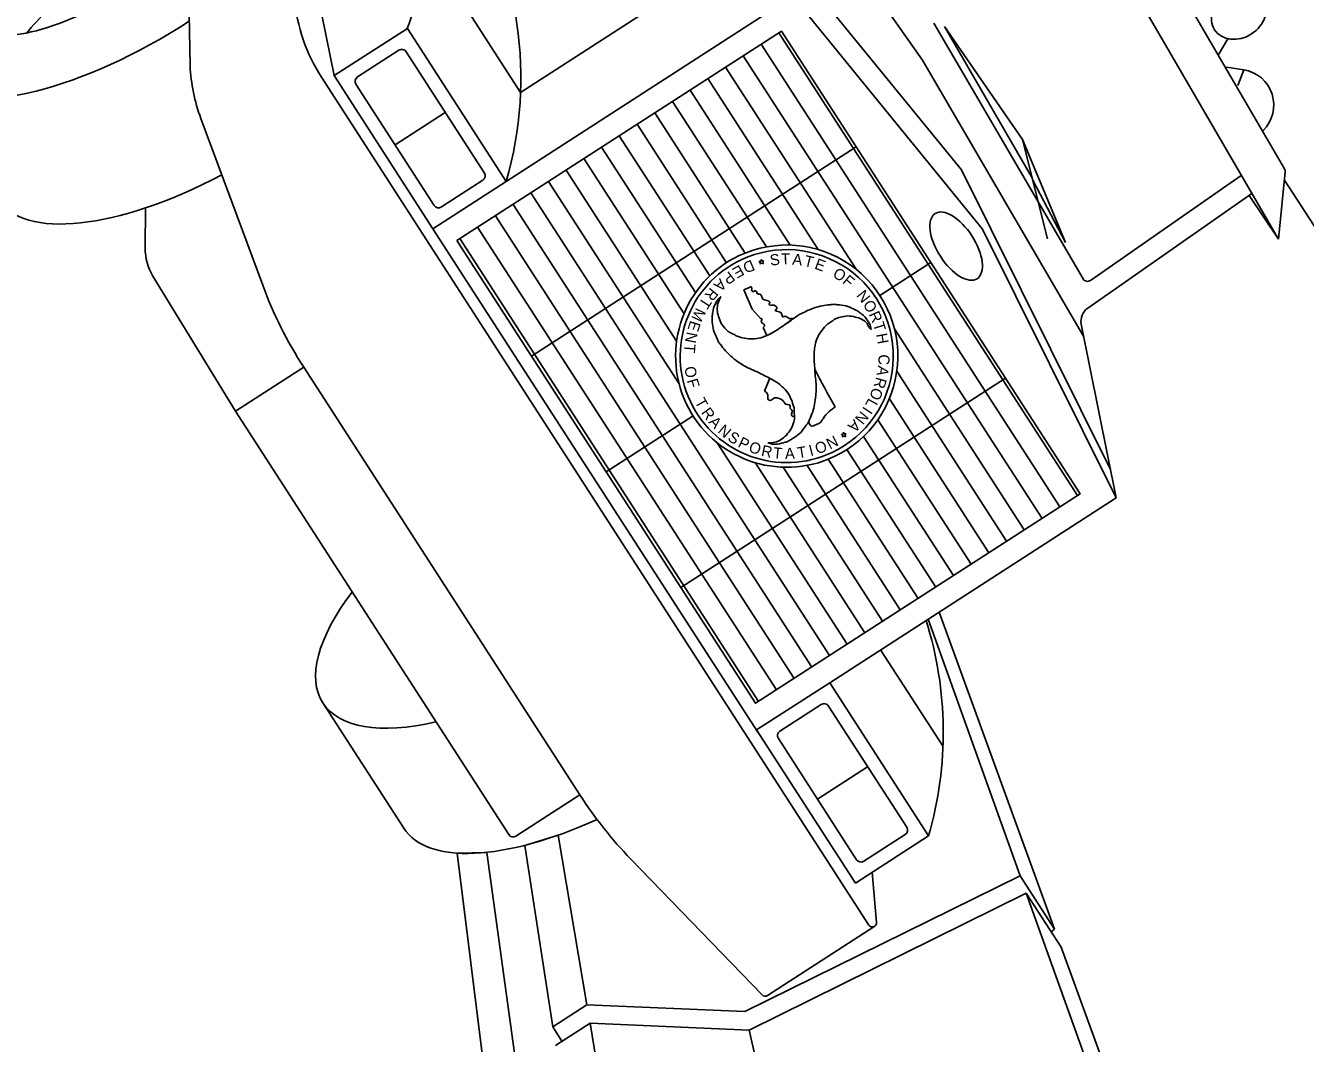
# Model space of a CAD drawing. Extents: x 2160312 to 2162215, y 789569 to 792090.
# Drawn here: x 2160615.79 to 2160662.65, y 791228.56 to 791265.83 of the extents above; entities that cross this region are included whole.
import ezdxf

# ---------------------------------------------------------------- set-up
doc = ezdxf.new("R2010")
doc.units = 0
doc.layers.add('DEV TITLE SHEET CELL', color=7, linetype='Continuous')

msp = doc.modelspace()

# ---------------------------------------------------------------- linework, layer by layer
at = {"layer": 'DEV TITLE SHEET CELL'}
for p, q in [((2160648.626, 791264.563), (2160640.264, 791276.54)), ((2160655.676, 791271.234), (2160661.886, 791260.593)), ((2160627.088, 791263.999), (2160625.964, 791269.539)), ((2160642.535, 791268.951), (2160633.917, 791263.388)), ((2160643.297, 791268.831), (2160650.056, 791260.549)), ((2160630.476, 791268.718), (2160633.917, 791263.388)), ((2160655.437, 791268.714), (2160661.659, 791258.006)), ((2160621.816, 791264.365), (2160621.745, 791268.133)), ((2160643.446, 791266.614), (2160633.389, 791260.122)), ((2160649.047, 791265.919), (2160654.507, 791256.561)), ((2160654.304, 791248.623), (2160643.367, 791265.566)), ((2160652.295, 791261.665), (2160649.431, 791265.803)), ((2160649.431, 791265.803), (2160652.654, 791260.228)), ((2160653.655, 791248.205), (2160642.718, 791265.147)), ((2160659.812, 791265.35), (2160659.457, 791264.755)), ((2160627.945, 791263.954), (2160629.458, 791264.93)), ((2160629.725, 791264.873), (2160632.59, 791260.434)), ((2160653.007, 791247.786), (2160642.07, 791264.729)), ((2160648.626, 791264.563), (2160654.537, 791254.434)), ((2160646.197, 791256.912), (2160641.422, 791264.31)), ((2160660.391, 791264.212), (2160659.765, 791264.311)), ((2160660.391, 791264.212), (2160660.176, 791263.635)), ((2160630.753, 791259.248), (2160627.888, 791263.687)), ((2160644.814, 791257.632), (2160640.773, 791263.892)), ((2160643.789, 791257.797), (2160640.125, 791263.473)), ((2160631.157, 791262.653), (2160629.32, 791261.467)), ((2160642.914, 791257.729), (2160639.476, 791263.054)), ((2160624.474, 791256.33), (2160622.21, 791262.434)), ((2160641.452, 791257.147), (2160638.179, 791262.217)), ((2160642.141, 791257.504), (2160638.828, 791262.636)), ((2160640.844, 791256.666), (2160637.531, 791261.799)), ((2160646.197, 791261.392), (2160634.319, 791253.724)), ((2160640.321, 791256.053), (2160636.882, 791261.38)), ((2160653.207, 791258.019), (2160652.295, 791261.665)), ((2160652.295, 791261.665), (2160653.865, 791257.889)), ((2160639.9, 791255.282), (2160636.234, 791260.961)), ((2160639.63, 791254.278), (2160635.585, 791260.543)), ((2160650.056, 791260.549), (2160655.516, 791249.582)), ((2160654.785, 791256.5), (2160660.297, 791260.349)), ((2160661.659, 791258.006), (2160661.911, 791260.477)), ((2160632.533, 791260.167), (2160631.02, 791259.19)), ((2160639.722, 791252.711), (2160634.937, 791260.124)), ((2160653.865, 791257.889), (2160652.67, 791260.167)), ((2160661.88, 791260.176), (2160704.37, 791194.597)), ((2160645.225, 791242.763), (2160634.288, 791259.706)), ((2160654.679, 791255.485), (2160660.687, 791259.68)), ((2160660.592, 791259.614), (2160661.659, 791258.006)), ((2160620.174, 791257.682), (2160620.187, 791259.156)), ((2160644.577, 791242.344), (2160633.64, 791259.287)), ((2160643.28, 791241.507), (2160632.343, 791258.45)), ((2160643.928, 791241.926), (2160632.992, 791258.868)), ((2160630.708, 791258.391), (2160642.605, 791239.961)), ((2160642.632, 791241.089), (2160631.695, 791258.031)), ((2160642.642, 791257.193), (2160642.712, 791257.203)), ((2160642.642, 791257.193), (2160642.712, 791257.203)), ((2160642.703, 791257.161), (2160642.642, 791257.193)), ((2160642.703, 791257.161), (2160642.642, 791257.193)), ((2160642.69, 791257.091), (2160642.703, 791257.161)), ((2160642.69, 791257.091), (2160642.703, 791257.161)), ((2160642.741, 791257.14), (2160642.69, 791257.091)), ((2160642.741, 791257.14), (2160642.69, 791257.091)), ((2160642.712, 791257.203), (2160642.726, 791257.272)), ((2160642.712, 791257.203), (2160642.726, 791257.272)), ((2160642.726, 791257.272), (2160642.756, 791257.208)), ((2160642.726, 791257.272), (2160642.756, 791257.208)), ((2160642.804, 791257.105), (2160642.741, 791257.14)), ((2160642.804, 791257.105), (2160642.741, 791257.14)), ((2160642.756, 791257.208), (2160642.823, 791257.218)), ((2160642.756, 791257.208), (2160642.823, 791257.218)), ((2160642.823, 791257.218), (2160642.774, 791257.169)), ((2160642.823, 791257.218), (2160642.774, 791257.169)), ((2160642.774, 791257.169), (2160642.804, 791257.105)), ((2160642.774, 791257.169), (2160642.804, 791257.105)), ((2160648.931, 791257.156), (2160647.069, 791255.954)), ((2160623.473, 791251.71), (2160620.456, 791256.662)), ((2160642.092, 791256.16), (2160642.317, 791256.256)), ((2160642.092, 791256.16), (2160642.317, 791256.256)), ((2160642.395, 791255.449), (2160642.092, 791256.16)), ((2160642.395, 791255.449), (2160642.092, 791256.16)), ((2160642.702, 791255.105), (2160642.395, 791255.449)), ((2160642.702, 791255.105), (2160642.395, 791255.449)), ((2160642.935, 791254.483), (2160642.801, 791254.775)), ((2160642.935, 791254.483), (2160642.801, 791254.775)), ((2160646.76, 791254.716), (2160646.75, 791254.719)), ((2160646.76, 791254.716), (2160646.75, 791254.719)), ((2160646.76, 791254.716), (2160646.75, 791254.719)), ((2160652.358, 791247.368), (2160647.605, 791254.731)), ((2160655.726, 791248.545), (2160654.443, 791254.896)), ((2160625.978, 791253.327), (2160623.473, 791251.71)), ((2160625.978, 791253.327), (2160636.089, 791237.663)), ((2160651.666, 791252.921), (2160639.787, 791245.253)), ((2160642.849, 791252.452), (2160643.038, 791252.919)), ((2160642.849, 791252.452), (2160643.038, 791252.919)), ((2160643.038, 791252.919), (2160643.038, 791252.919)), ((2160643.038, 791252.919), (2160643.038, 791252.919)), ((2160644.686, 791253.255), (2160644.686, 791253.255)), ((2160644.686, 791253.255), (2160644.686, 791253.255)), ((2160651.71, 791246.949), (2160647.692, 791253.173)), ((2160651.062, 791246.53), (2160647.42, 791252.171)), ((2160623.473, 791251.71), (2160633.48, 791236.208)), ((2160640.232, 791251.541), (2160637.053, 791249.489)), ((2160650.413, 791246.112), (2160646.998, 791251.402)), ((2160645.738, 791250.942), (2160645.726, 791250.872)), ((2160645.738, 791250.942), (2160645.726, 791250.872)), ((2160645.768, 791250.879), (2160645.738, 791250.942)), ((2160645.768, 791250.879), (2160645.738, 791250.942)), ((2160645.874, 791243.182), (2160641.111, 791250.559)), ((2160645.726, 791250.872), (2160645.656, 791250.862)), ((2160645.726, 791250.872), (2160645.656, 791250.862)), ((2160645.656, 791250.862), (2160645.716, 791250.83)), ((2160645.656, 791250.862), (2160645.716, 791250.83)), ((2160645.716, 791250.83), (2160645.703, 791250.762)), ((2160645.716, 791250.83), (2160645.703, 791250.762)), ((2160645.703, 791250.762), (2160645.756, 791250.809)), ((2160645.703, 791250.762), (2160645.756, 791250.809)), ((2160645.756, 791250.809), (2160645.819, 791250.776)), ((2160645.756, 791250.809), (2160645.819, 791250.776)), ((2160645.836, 791250.887), (2160645.768, 791250.879)), ((2160645.836, 791250.887), (2160645.768, 791250.879)), ((2160645.788, 791250.837), (2160645.836, 791250.887)), ((2160645.788, 791250.837), (2160645.836, 791250.887)), ((2160645.819, 791250.776), (2160645.788, 791250.837)), ((2160645.819, 791250.776), (2160645.788, 791250.837)), ((2160649.765, 791245.693), (2160646.474, 791250.79)), ((2160645.399, 791250.051), (2160645.399, 791250.051)), ((2160645.399, 791250.051), (2160645.399, 791250.051)), ((2160649.116, 791245.275), (2160645.866, 791250.31)), ((2160646.522, 791243.6), (2160642.501, 791249.83)), ((2160647.171, 791244.019), (2160643.527, 791249.663)), ((2160647.819, 791244.437), (2160644.403, 791249.729)), ((2160648.468, 791244.856), (2160645.177, 791249.954)), ((2160655.726, 791248.545), (2160645.235, 791241.772)), ((2160652.201, 791234.704), (2160648.838, 791244.098)), ((2160649.236, 791244.355), (2160653.464, 791232.749)), ((2160647.095, 791242.973), (2160649.382, 791239.431)), ((2160626.676, 791241.03), (2160629.637, 791236.443)), ((2160643.41, 791239.996), (2160644.923, 791240.973)), ((2160645.19, 791240.916), (2160648.055, 791236.477)), ((2160646.218, 791235.291), (2160643.353, 791239.73)), ((2160646.622, 791238.696), (2160644.785, 791237.51)), ((2160636.089, 791237.663), (2160633.747, 791236.151)), ((2160634.069, 791235.816), (2160635.298, 791236.19)), ((2160635.298, 791236.19), (2160636.345, 791229.978)), ((2160647.998, 791236.21), (2160646.485, 791235.233)), ((2160632.683, 791235.56), (2160631.597, 791235.53)), ((2160631.597, 791235.53), (2160634.863, 791209.37)), ((2160636.663, 791206.583), (2160632.683, 791235.56)), ((2160635.091, 791229.169), (2160634.069, 791235.816)), ((2160642.757, 791230.339), (2160637.954, 791235.312)), ((2160652.201, 791234.704), (2160642.128, 791229.726)), ((2160646.788, 791234.831), (2160646.95, 791232.995)), ((2160652.201, 791234.704), (2160653.464, 791232.749)), ((2160652.431, 791234.063), (2160642.284, 791229.049)), ((2160652.431, 791234.063), (2160653.703, 791232.093)), ((2160660.527, 791211.45), (2160652.431, 791234.063)), ((2160642.951, 791230.316), (2160646.88, 791232.852)), ((2160653.464, 791232.749), (2160653.343, 791232.65)), ((2160653.703, 791232.093), (2160661.09, 791211.813)), ((2160636.345, 791229.978), (2160635.091, 791229.169)), ((2160642.128, 791229.726), (2160636.345, 791229.978)), ((2160635.091, 791229.169), (2160635.432, 791228.64)), ((2160636.459, 791229.303), (2160635.196, 791228.487)), ((2160642.284, 791229.049), (2160636.459, 791229.303)), ((2160636.459, 791229.303), (2160641.533, 791199.208)), ((2160648.173, 791203.488), (2160642.284, 791229.049))]:
    msp.add_line(p, q, dxfattribs=at)
for points in [[(2160644.208, 791266.493), (2160650.828, 791258.381), (2160655.726, 791248.545)], [(2160646.666, 791232.898), (2160626.629, 791263.938)]]:
    msp.add_lwpolyline(points, dxfattribs=at)
for points in [[(2160630.708, 791258.391), (2160627.088, 791263.999), (2160629.77, 791265.729), (2160633.389, 791260.122)], [(2160631.584, 791257.96), (2160642.521, 791241.017), (2160654.4, 791248.685), (2160643.463, 791265.628)], [(2160646.173, 791234.434), (2160642.553, 791240.041), (2160645.235, 791241.772), (2160648.854, 791236.165)]]:
    msp.add_lwpolyline(points, close=True, dxfattribs=at)
for centre, radius, start, end in [((2160620.295, 791263.912), 13.632, 343.8569, 32.8433), ((2160618.976, 791269.857), 11.556, 339.0716, 354.3432), ((2160631.977, 791267.39), 6.365, 185.032, 212.8433), ((2160629.563, 791264.768), 0.193, 32.8433, 122.8433), ((2160628.242, 791264.671), 6.434, 182.7302, 200.3503), ((2160660.186, 791262.922), 1.306, 314.5789, 80.9868), ((2160628.05, 791263.791), 0.193, 122.8433, 212.8433), ((2160632.428, 791260.329), 0.193, 302.8433, 32.8433), ((2160661.719, 791260.496), 0.193, 354.178, 30.2653), ((2160630.915, 791259.352), 0.193, 212.8433, 302.8433), ((2160622.104, 791257.666), 1.93, 179.5152, 211.3512), ((2160643.661, 791253.73), 4.069, 295.2645, 115.2645), ((2160643.661, 791253.73), 4.069, 295.2645, 115.2645), ((2160643.661, 791253.73), 3.899, 295.2645, 115.2645), ((2160643.661, 791253.73), 3.899, 295.2645, 115.2645), ((2160643.661, 791253.73), 4.069, 115.2645, 295.2645), ((2160643.661, 791253.73), 4.069, 115.2645, 295.2645), ((2160643.661, 791253.73), 3.899, 115.2645, 295.2645), ((2160643.661, 791253.73), 3.899, 115.2645, 295.2645), ((2160654.674, 791256.658), 0.193, 210.2653, 304.9228), ((2160638.947, 791261.698), 15.437, 200.3503, 212.8433), ((2160655.011, 791255.011), 0.579, 124.9228, 191.4158), ((2160663.905, 791262.788), 21.453, 200.943, 201.0426), ((2160663.905, 791262.788), 21.453, 200.943, 201.0426), ((2160663.905, 791262.788), 21.453, 206.382, 210.588), ((2160663.905, 791262.788), 21.453, 206.382, 210.588), ((2160635.76, 791239.955), 13.632, 343.8569, 17.4785), ((2160645.028, 791240.811), 0.193, 32.8433, 122.8433), ((2160643.515, 791239.834), 0.193, 122.8433, 212.8433), ((2160649.058, 791246.035), 15.437, 212.8433, 224.0004), ((2160647.893, 791236.372), 0.193, 302.8433, 32.8433), ((2160633.642, 791236.313), 0.193, 212.8433, 302.8433), ((2160646.38, 791235.395), 0.193, 212.8433, 302.8433), ((2160646.796, 791232.982), 0.154, 212.8433, 5.032), ((2160642.868, 791230.446), 0.154, 224.0004, 302.8433)]:
    msp.add_arc(centre, radius, start, end, dxfattribs=at)
for centre, major_axis, ratio, start_param, end_param in [((2160619.652, 791269.146), (7.853, 5.07), 0.407167, 5.343461, 11.004346), ((2160620.546, 791267.389), (-5.233, -3.378), 0.26845, 5.11804, 5.631746), ((2160622.613, 791264.56), (7.853, 5.07), 0.407167, 3.141593, 4.500187), ((2160634.53, 791246.1), (7.853, 5.07), 0.407167, 2.302633, 3.980552), ((2160637.49, 791241.513), (7.853, 5.07), 0.407167, 3.141593, 4.359994)]:
    msp.add_ellipse(centre, major_axis=major_axis, ratio=ratio, start_param=start_param, end_param=end_param, dxfattribs=at)
for centre, major_axis, ratio in [((2160619.652, 791269.146), (-5.233, -3.378), 0.26845), ((2160660.211, 791266.248), (0.887, 0.573), 0.8125), ((2160649.862, 791257.757), (-0.77, 1.193), 0.48463)]:
    msp.add_ellipse(centre, major_axis=major_axis, ratio=ratio, dxfattribs=at)
for points in [[(2160642.317, 791256.256), (2160642.334, 791256.274), (2160642.375, 791256.248), (2160642.382, 791256.124), (2160642.451, 791256.093), (2160642.495, 791256.116), (2160642.559, 791256.096), (2160642.578, 791256.018), (2160642.691, 791255.993), (2160642.733, 791255.941), (2160642.791, 791255.816), (2160643.009, 791255.739), (2160643.047, 791255.681), (2160643.015, 791255.647), (2160643.025, 791255.605), (2160643.177, 791255.6), (2160643.203, 791255.592), (2160643.303, 791255.498), (2160643.296, 791255.457), (2160643.245, 791255.422), (2160643.242, 791255.401), (2160643.287, 791255.376), (2160643.377, 791255.355), (2160643.471, 791255.283), (2160643.509, 791255.169), (2160643.606, 791255.192), (2160643.75, 791255.106), (2160643.814, 791255.104), (2160643.869, 791255.122)], [(2160642.317, 791256.256), (2160642.334, 791256.274), (2160642.375, 791256.248), (2160642.382, 791256.124), (2160642.451, 791256.093), (2160642.495, 791256.116), (2160642.559, 791256.096), (2160642.578, 791256.018), (2160642.691, 791255.993), (2160642.733, 791255.941), (2160642.791, 791255.816), (2160643.009, 791255.739), (2160643.047, 791255.681), (2160643.015, 791255.647), (2160643.025, 791255.605), (2160643.177, 791255.6), (2160643.203, 791255.592), (2160643.303, 791255.498), (2160643.296, 791255.457), (2160643.245, 791255.422), (2160643.242, 791255.401), (2160643.287, 791255.376), (2160643.377, 791255.355), (2160643.471, 791255.283), (2160643.509, 791255.169), (2160643.606, 791255.192), (2160643.75, 791255.106), (2160643.814, 791255.104), (2160643.869, 791255.122)], [(2160641.252, 791255.913), (2160641.182, 791255.847), (2160641.036, 791255.62), (2160640.95, 791255.344), (2160640.948, 791255.319), (2160640.928, 791255.161), (2160640.936, 791254.981), (2160640.98, 791254.679), (2160641.096, 791254.398), (2160641.146, 791254.278), (2160641.233, 791254.155), (2160641.415, 791253.924), (2160641.613, 791253.727), (2160641.872, 791253.526), (2160642.107, 791253.37), (2160642.374, 791253.241), (2160642.645, 791253.117), (2160642.902, 791252.988), (2160643.165, 791252.852), (2160643.405, 791252.69), (2160643.427, 791252.669), (2160643.653, 791252.45), (2160643.802, 791252.196), (2160643.898, 791251.937), (2160643.932, 791251.794), (2160643.936, 791251.624), (2160643.948, 791251.522), (2160643.917, 791251.319), (2160643.812, 791251.054), (2160643.646, 791250.84), (2160643.456, 791250.676), (2160643.223, 791250.579), (2160642.969, 791250.553)], [(2160641.252, 791255.913), (2160641.182, 791255.847), (2160641.036, 791255.62), (2160640.95, 791255.344), (2160640.948, 791255.319), (2160640.928, 791255.161), (2160640.936, 791254.981), (2160640.98, 791254.679), (2160641.096, 791254.398), (2160641.146, 791254.278), (2160641.233, 791254.155), (2160641.415, 791253.924), (2160641.613, 791253.727), (2160641.872, 791253.526), (2160642.107, 791253.37), (2160642.374, 791253.241), (2160642.645, 791253.117), (2160642.902, 791252.988), (2160643.165, 791252.852), (2160643.405, 791252.69), (2160643.427, 791252.669), (2160643.653, 791252.45), (2160643.802, 791252.196), (2160643.898, 791251.937), (2160643.932, 791251.794), (2160643.936, 791251.624), (2160643.948, 791251.522), (2160643.917, 791251.319), (2160643.812, 791251.054), (2160643.646, 791250.84), (2160643.456, 791250.676), (2160643.223, 791250.579), (2160642.969, 791250.553)], [(2160646.75, 791254.719), (2160646.732, 791254.812), (2160646.607, 791255.051), (2160646.41, 791255.263), (2160646.388, 791255.279), (2160646.264, 791255.372), (2160646.104, 791255.458), (2160645.821, 791255.568), (2160645.516, 791255.611), (2160645.388, 791255.626), (2160645.245, 791255.613), (2160644.947, 791255.572), (2160644.676, 791255.496), (2160644.375, 791255.374), (2160644.119, 791255.248), (2160643.877, 791255.082), (2160643.633, 791254.911), (2160643.394, 791254.751), (2160643.146, 791254.59), (2160642.884, 791254.465), (2160642.86, 791254.455), (2160642.558, 791254.37), (2160642.259, 791254.367), (2160641.984, 791254.416), (2160641.848, 791254.458), (2160641.694, 791254.536), (2160641.605, 791254.579), (2160641.442, 791254.706), (2160641.264, 791254.93), (2160641.162, 791255.183), (2160641.114, 791255.428), (2160641.147, 791255.678), (2160641.252, 791255.913)], [(2160646.75, 791254.719), (2160646.732, 791254.812), (2160646.607, 791255.051), (2160646.41, 791255.263), (2160646.388, 791255.279), (2160646.264, 791255.372), (2160646.104, 791255.458), (2160645.821, 791255.568), (2160645.516, 791255.611), (2160645.388, 791255.626), (2160645.245, 791255.613), (2160644.947, 791255.572), (2160644.676, 791255.496), (2160644.375, 791255.374), (2160644.119, 791255.248), (2160643.877, 791255.082), (2160643.633, 791254.911), (2160643.394, 791254.751), (2160643.146, 791254.59), (2160642.884, 791254.465), (2160642.86, 791254.455), (2160642.558, 791254.37), (2160642.259, 791254.367), (2160641.984, 791254.416), (2160641.848, 791254.458), (2160641.694, 791254.536), (2160641.605, 791254.579), (2160641.442, 791254.706), (2160641.264, 791254.93), (2160641.162, 791255.183), (2160641.114, 791255.428), (2160641.147, 791255.678), (2160641.252, 791255.913)], [(2160642.969, 791250.553), (2160643.055, 791250.524), (2160643.327, 791250.511), (2160643.608, 791250.576), (2160643.635, 791250.584), (2160643.777, 791250.648), (2160643.932, 791250.745), (2160644.171, 791250.932), (2160644.357, 791251.176), (2160644.436, 791251.278), (2160644.497, 791251.411), (2160644.61, 791251.688), (2160644.68, 791251.96), (2160644.723, 791252.282), (2160644.74, 791252.566), (2160644.72, 791252.862), (2160644.693, 791253.156), (2160644.675, 791253.441), (2160644.659, 791253.741), (2160644.682, 791254.028), (2160644.687, 791254.053), (2160644.763, 791254.361), (2160644.912, 791254.621), (2160645.089, 791254.835), (2160645.194, 791254.927), (2160645.339, 791255.023), (2160645.421, 791255.081), (2160645.613, 791255.155), (2160645.897, 791255.199), (2160646.165, 791255.161), (2160646.4, 791255.079), (2160646.601, 791254.924), (2160646.75, 791254.719), (2160646.76, 791254.716)], [(2160642.969, 791250.553), (2160643.055, 791250.524), (2160643.327, 791250.511), (2160643.608, 791250.576), (2160643.635, 791250.584), (2160643.777, 791250.648), (2160643.932, 791250.745), (2160644.171, 791250.932), (2160644.357, 791251.176), (2160644.436, 791251.278), (2160644.497, 791251.411), (2160644.61, 791251.688), (2160644.68, 791251.96), (2160644.723, 791252.282), (2160644.74, 791252.566), (2160644.72, 791252.862), (2160644.693, 791253.156), (2160644.675, 791253.441), (2160644.659, 791253.741), (2160644.682, 791254.028), (2160644.687, 791254.053), (2160644.763, 791254.361), (2160644.912, 791254.621), (2160645.089, 791254.835), (2160645.194, 791254.927), (2160645.339, 791255.023), (2160645.421, 791255.081), (2160645.613, 791255.155), (2160645.897, 791255.199), (2160646.165, 791255.161), (2160646.4, 791255.079), (2160646.601, 791254.924), (2160646.75, 791254.719), (2160646.76, 791254.716)], [(2160642.801, 791254.775), (2160642.841, 791254.829), (2160642.831, 791254.893), (2160642.754, 791254.951), (2160642.73, 791255.01), (2160642.746, 791255.095), (2160642.702, 791255.105)], [(2160642.801, 791254.775), (2160642.841, 791254.829), (2160642.831, 791254.893), (2160642.754, 791254.951), (2160642.73, 791255.01), (2160642.746, 791255.095), (2160642.702, 791255.105)], [(2160643.883, 791255.086), (2160643.877, 791255.082), (2160643.633, 791254.911), (2160643.394, 791254.751), (2160643.146, 791254.59), (2160642.935, 791254.484)], [(2160643.883, 791255.086), (2160643.877, 791255.082), (2160643.633, 791254.911), (2160643.394, 791254.751), (2160643.146, 791254.59), (2160642.935, 791254.484)], [(2160643.038, 791252.919), (2160643.165, 791252.852), (2160643.405, 791252.69), (2160643.427, 791252.669), (2160643.653, 791252.45), (2160643.802, 791252.196), (2160643.898, 791251.937), (2160643.932, 791251.794), (2160643.936, 791251.624), (2160643.946, 791251.529)], [(2160643.038, 791252.919), (2160643.165, 791252.852), (2160643.405, 791252.69), (2160643.427, 791252.669), (2160643.653, 791252.45), (2160643.802, 791252.196), (2160643.898, 791251.937), (2160643.932, 791251.794), (2160643.936, 791251.624), (2160643.946, 791251.529)], [(2160644.462, 791251.324), (2160644.497, 791251.411), (2160644.61, 791251.688), (2160644.68, 791251.96), (2160644.723, 791252.282), (2160644.74, 791252.566), (2160644.72, 791252.862), (2160644.693, 791253.156), (2160644.686, 791253.255)], [(2160644.462, 791251.324), (2160644.497, 791251.411), (2160644.61, 791251.688), (2160644.68, 791251.96), (2160644.723, 791252.282), (2160644.74, 791252.566), (2160644.72, 791252.862), (2160644.693, 791253.156), (2160644.686, 791253.255)], [(2160643.945, 791251.529), (2160643.865, 791251.533), (2160643.834, 791251.586), (2160643.866, 791251.72), (2160643.786, 791251.827), (2160643.791, 791251.897), (2160643.776, 791251.933), (2160643.627, 791251.969), (2160643.545, 791252.074), (2160643.314, 791252.198), (2160643.214, 791252.199), (2160643.044, 791252.102), (2160642.987, 791252.132), (2160642.969, 791252.193), (2160642.959, 791252.332), (2160642.849, 791252.452)], [(2160643.945, 791251.529), (2160643.865, 791251.533), (2160643.834, 791251.586), (2160643.866, 791251.72), (2160643.786, 791251.827), (2160643.791, 791251.897), (2160643.776, 791251.933), (2160643.627, 791251.969), (2160643.545, 791252.074), (2160643.314, 791252.198), (2160643.214, 791252.199), (2160643.044, 791252.102), (2160642.987, 791252.132), (2160642.969, 791252.193), (2160642.959, 791252.332), (2160642.849, 791252.452)], [(2160645.437, 791251.872), (2160645.216, 791251.704), (2160644.988, 791251.439), (2160644.869, 791251.281), (2160644.731, 791251.219), (2160644.554, 791251.174), (2160644.464, 791251.323)], [(2160645.437, 791251.872), (2160645.216, 791251.704), (2160644.988, 791251.439), (2160644.869, 791251.281), (2160644.731, 791251.219), (2160644.554, 791251.174), (2160644.464, 791251.323)]]:
    msp.add_spline(points, degree=3, dxfattribs=at)

# ---------------------------------------------------------------- texts
for s, height, rotation, p in [('T', 0.407, 0.6446, (2160643.451, 791257.085)), ('E', 0.404, 209.4054, (2160641.945, 791257.084)), ('D', 0.406, 203.1175, (2160642.372, 791257.27)), ('S', 0.405, 7.0207, (2160643.068, 791257.039)), ('A', 0.407, 353.5923, (2160643.848, 791257.084)), ('T', 0.405, 346.537, (2160644.265, 791257.037)), ('E', 0.404, 339.4214, (2160644.65, 791256.943)), ('A', 0.405, 223.5303, (2160641.219, 791256.6)), ('P', 0.406, 216.9378, (2160641.565, 791256.86)), ('O', 0.406, 327.482, (2160645.311, 791256.657)), ('F', 0.407, 320.3352, (2160645.671, 791256.425)), ('R', 0.406, 230.599, (2160640.874, 791256.265)), ('N', 0.406, 308.2482, (2160646.19, 791255.945)), ('T', 0.405, 237.2495, (2160640.593, 791255.916)), ('O', 0.407, 300.7501, (2160646.433, 791255.632)), ('M', 0.405, 244.4845, (2160640.349, 791255.525)), ('R', 0.406, 294.1402, (2160646.653, 791255.264)), ('E', 0.405, 251.9513, (2160640.135, 791255.056)), ('T', 0.407, 287.4906, (2160646.812, 791254.909)), ('N', 0.406, 258.9229, (2160640.004, 791254.638)), ('H', 0.405, 280.4059, (2160646.928, 791254.53)), ('T', 0.405, 265.7649, (2160639.92, 791254.188)), ('C', 0.405, 268.0635, (2160647.024, 791253.801)), ('O', 0.405, 279.0685, (2160639.914, 791253.322)), ('A', 0.405, 260.5665, (2160647.008, 791253.396)), ('F', 0.405, 286.2338, (2160639.998, 791252.839)), ('R', 0.405, 254.2025, (2160646.941, 791252.986)), ('O', 0.406, 247.0829, (2160646.834, 791252.613)), ('T', 0.404, 299.143, (2160640.281, 791252.059)), ('R', 0.406, 306.0996, (2160640.509, 791251.66)), ('I', 0.406, 236.8599, (2160646.489, 791251.912)), ('L', 0.405, 240.8493, (2160646.666, 791252.215)), ('A', 0.404, 312.8527, (2160640.778, 791251.302)), ('A', 0.406, 223.7278, (2160646.126, 791251.44)), ('N', 0.406, 231.1598, (2160646.378, 791251.748)), ('N', 0.404, 319.8844, (2160641.11, 791250.955)), ('S', 0.404, 327.0948, (2160641.466, 791250.666)), ('P', 0.406, 334.2867, (2160641.844, 791250.425)), ('O', 0.407, 340.9787, (2160642.237, 791250.239)), ('R', 0.406, 348.1678, (2160642.702, 791250.083)), ('I', 0.407, 15.089, (2160644.533, 791250.06)), ('O', 0.404, 20.2246, (2160644.784, 791250.13)), ('N', 0.406, 27.4726, (2160645.242, 791250.304)), ('T', 0.404, 354.2676, (2160643.143, 791249.996)), ('A', 0.407, 2.3546, (2160643.601, 791249.957)), ('T', 0.405, 9.4391, (2160644.081, 791249.983))]:
    msp.add_text(s, height=height, rotation=rotation, dxfattribs=at).set_placement(p)

doc.saveas('drawing.dxf')
